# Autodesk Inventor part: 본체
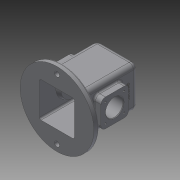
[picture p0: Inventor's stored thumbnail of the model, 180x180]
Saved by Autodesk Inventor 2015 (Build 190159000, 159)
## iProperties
Created: 2021-08
Part Number: 본체
Material: 일반
Document SubType Name: Modeling
Designer: 103-20
Density: 1 g/cm^3
Appearance: 기본값
Mass: 246.458 g
Surface Area: 996.247 cm^2
Volume: 246.458 cm^3
Author: 103-20
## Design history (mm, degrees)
sketch "스케치1"
  geometry: C1 r 67 at (0, 0); 1 further point
  constraints: 1 centre point, 1 coincident
  dimensions: "d0" = 134 diameter of C1
extrude "돌출1" new body sketch "스케치1" distance "d1" = 10; taper "d2" = 0 deg
sketch "스케치2"
  geometry: C1 r 67 at (0, 0) reference; C2 r 4.5 at (0, 55); C3 r 4.5 at (0, -55); A1 r 55 centre (0, 0) between (0, 55) and (0, -55)
  constraints: 3 centre point, 2 point on circle, 1 coincident
  dimensions: "d3" = 110 diameter of A1; "d4" = 9 diameter of C2; "d5" = 9 diameter of C3
extrude "돌출2" cut sketch "스케치2" distance "d6" = 10; taper "d7" = 0 deg
sketch "스케치3"
  geometry: L1 (37, -37)-(-37, -37); L2 (-37, -37)-(-37, 37); L3 (-37, 37)-(37, 37); L4 (37, 37)-(37, -37); L5 (37, -37)-(-37, 37); L6 (-37, -37)-(37, 37); C1 r 67 at (0, 0) reference
  constraints: 12 end point, 2 midpoint, 2 parallel, 1 horizontal, 1 perpendicular
  dimensions: "d8" = 74 distance of L2.end L3.end; "d9" = 74 distance of L3.end L1.start
extrude "돌출3" join sketch "스케치3" distance "d10" = 100; taper "d11" = 0 deg
sketch "스케치4"
  geometry: C1 r 20 at (0, 0); 1 further point
  constraints: 1 centre point, 1 coincident
  dimensions: "d12" = 40 diameter of C1
extrude "돌출4" join sketch "스케치4" distance "d13" = 10; taper "d14" = 0 deg
sketch "스케치5"
  geometry: L1 (0, 100)-(74, 100) reference; L2 (12, 70)-(62, 70); L3 (62, 70)-(62, 20); L4 (62, 20)-(12, 20); L5 (12, 20)-(12, 70); L6 (12, 70)-(62, 20); L7 (62, 70)-(12, 20); L8 (-30, -10)-(104, -10) reference; 4 further points
  constraints: 12 end point, 4 midpoint, 2 parallel, 1 horizontal, 1 perpendicular, 1 vertical alignment
  dimensions: "d15" = 50 distance of L2.start L2.end; "d16" = 50 distance of L2.end L3.end; "d17" = 55 distance from line of L8 point (37, 45); "d18" = 37 horizontal distance of L1.start point (37, 45) (derived)
extrude "돌출5" join sketch "스케치5" distance "d19" = 13; taper "d20" = 0 deg
sketch "스케치6"
  geometry: L1 (32, -32)-(-32, -32); L2 (-32, -32)-(-32, 32); L3 (-32, 32)-(32, 32); L4 (32, 32)-(32, -32); L5 (32, -32)-(-32, 32); L6 (-32, -32)-(32, 32); C1 r 67 at (0, 0) reference
  constraints: 12 end point, 2 midpoint, 2 parallel, 1 horizontal, 1 perpendicular
  dimensions: "d21" = 64 distance of L2.end L3.end; "d22" = 64 distance of L3.end L1.start
extrude "돌출6" cut sketch "스케치6" distance "d23" = 105; taper "d24" = 0 deg
fillet "모깎기1" dims "d25" = 3
sketch "스케치9"
  geometry: L1 (58, 0)-(0, 0) reference; L2 (-38, 0)-(96, 0) reference; L3 (-8, 10)-(-8, 110) reference; C1 r 25 at (29, 55); 2 further points
  constraints: 1 centre point, 1 midpoint, 1 vertical alignment
  dimensions: "d31" = 55 distance from line of L2 C1.centre; "d32" = 37 distance from line of L3 C1.centre (derived); "d40" = 50 diameter of C1
extrude "돌출7" join sketch "스케치9" distance "d33" = 7; taper "d34" = -20 deg
sketch "스케치10"
  geometry: L1 (-30, -10)-(104, -10) reference; L2 (0, 0)-(0, 100) reference; C1 r 16 at (37, 45); 1 further point
  constraints: 1 centre point
  dimensions: "d35" = 32 diameter of C1; "d36" = 55 distance from line of L1 C1.centre; "d37" = 37 distance from line of L2 C1.centre
extrude "돌출8" cut sketch "스케치10" distance "d38" = 30; taper "d39" = 0 deg
fillet "모깎기3" dims "d42" = 8
fillet "모깎기4" dims "d43" = 3
sketch "스케치13"
  geometry: A1 r 8 centre (20, 62) between (20, 70) and (12, 62) reference; A2 r 8 centre (20, 28) between (12, 28) and (20, 20) reference; A3 r 8 centre (54, 28) between (54, 20) and (62, 28) reference; A4 r 8 centre (54, 62) between (62, 62) and (54, 70) reference; 1 further point
hole "구멍2" sketch "스케치13" at (54, 62), (54, 28), (20, 62), (20, 28) diameter "d51" = 3.242; stored, may be unused: countersink angle "d55" = 90 deg, drill point angle "d57" = 118 deg; dims "d52" = 8, "d53" = 4, "d54" = 2, "d56" = 10
sketch "스케치14"
  geometry: C1 r 20 at (0, 0) reference; C2 r 14 at (0, 0)
  constraints: 1 centre point, 1 coincident
  dimensions: "d58" = 28 diameter of C2
extrude "돌출9" cut sketch "스케치14" distance "d59" = 4; taper "d60" = 0 deg
sketch "스케치15"
  geometry: C1 r 14 at (0, 0) reference; C2 r 10.5 at (0, 0)
  constraints: 1 centre point, 1 coincident
  dimensions: "d61" = 21 diameter of C2
extrude "돌출10" cut sketch "스케치15" distance "d62" = 20; taper "d63" = 0 deg
fillet "모깎기6" dims "d65" = 8
fillet "모깎기7" dims "d66" = 3
sketch "스케치16"
  geometry: L1 (49, 18)-(9, 18) reference; L2 (-8, 0)-(-8, -89) reference; 2 further points
  constraints: 1 other
  dimensions: "d67" = 28 distance from line of L1 point (29, -10); "d68" = 37 distance from line of L2 point (29, -10)
feature "엠보싱1" sketch "스케치16" dims "d69" = 1, "d70" = 0
fillet "모깎기8" dims "d71" = 3
chamfer "모따기1" distance "d72" = 1; stored, may be unused: second distance "d73" = 2, angle "d74" = 45 deg
sketch "스케치17"
  geometry: C1 r 20 at (0, 0) reference; C2 r 15 at (0, 0) reference
extrude "돌출11" join sketch "스케치17" stored distance "d75" = 20; taper "d76" = 6 deg
fillet "모깎기9" dims "d77" = 3
node "솔리드1"
mirror "대칭1"
mirror "대칭2"
